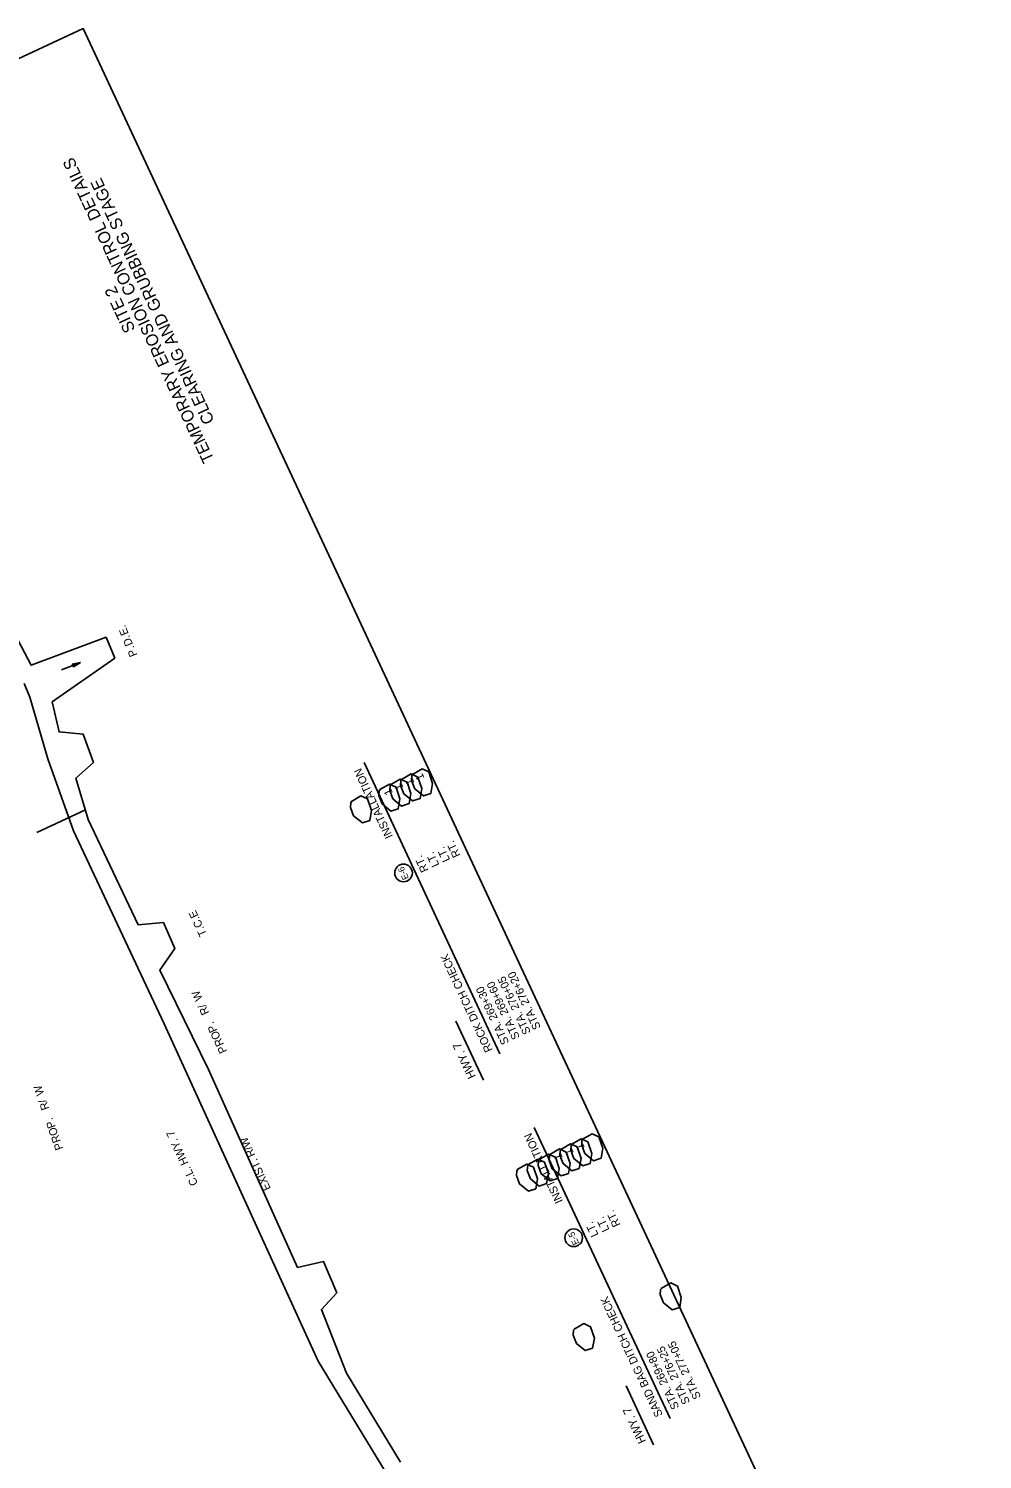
# Model space of a CAD drawing. Extents: x 964229 to 965790, y 1899262 to 1901428.
# Drawn here: x 965075 to 965790, y 1900076 to 1901149 of the extents above; entities that cross this region are included whole.
import ezdxf

# ---------------------------------------------------------------- set-up
doc = ezdxf.new("R2010")
doc.units = 0
for name, color, linetype in [('1', 7, 'Continuous'), ('43', 7, 'Continuous'), ('44', 7, 'Continuous'), ('60', 7, 'Continuous'), ('NO PLOT', 7, 'Continuous'), ('R_Draft', 7, 'Continuous'), ('R_Horz Alg Annot', 7, 'Continuous'), ('S_TREE', 7, 'Continuous')]:
    doc.layers.add(name, color=color, linetype=linetype)

msp = doc.modelspace()

# ---------------------------------------------------------------- linework, layer by layer
at = {"layer": '1'}
for centre in [(965355.7, 1900515.4), (965483.3, 1900241.8)]:
    msp.add_circle(centre, 6.61, dxfattribs=at)
at = {"layer": '43'}
for p, q in [((965107.3, 1900672), (965113.4, 1900673.2)), ((965108.1, 1900670), (965107.3, 1900672)), ((965113.4, 1900673.2), (965108.1, 1900670))]:
    msp.add_line(p, q, dxfattribs=at)
msp.add_lwpolyline([(965099.2, 1900667.8), (965113.4, 1900673.2)], dxfattribs=at)
at = {"layer": '44'}
for p, q in [((965428, 1900379.8), (965326.2, 1900598.2)), ((965415.6, 1900360), (965395, 1900404.3)), ((965555.6, 1900106.2), (965453.7, 1900324.6)), ((965543.2, 1900086.4), (965522.6, 1900130.7))]:
    msp.add_line(p, q, dxfattribs=at)
at = {"layer": 'NO PLOT'}
msp.add_lwpolyline([(965789.8, 1899702.7), (965115.5, 1901148.6), (964643.2, 1900928.4), (964770.4, 1900655.6), (964831.6, 1900684.1), (965011.2, 1900298.9), (964950, 1900270.4), (965071, 1900011), (965127, 1900037.1), (965271.8, 1899726.6), (965215.8, 1899700.5), (965317.4, 1899482.5)], close=True, dxfattribs=at)
msp.add_lwpolyline([(965789.8, 1899702.7), (965115.5, 1901148.6), (964643.2, 1900928.4), (964770.4, 1900655.6), (964831.6, 1900684.1), (965011.2, 1900298.9), (964950, 1900270.4), (965071, 1900011), (965127, 1900037.1), (965271.8, 1899726.6), (965215.8, 1899700.5), (965317.4, 1899482.5)], close=True, dxfattribs=at)
msp.add_lwpolyline([(965789.8, 1899702.7), (965115.5, 1901148.6), (964643.2, 1900928.4), (964770.4, 1900655.6), (964831.6, 1900684.1), (965011.2, 1900298.9), (964950, 1900270.4), (965071, 1900011), (965127, 1900037.1), (965271.8, 1899726.6), (965215.8, 1899700.5), (965317.4, 1899482.5)], close=True, dxfattribs=at)
for points in [[(965353.5, 1900073.5), (965312.9, 1900140.2), (965294.1, 1900188.1), (965305.6, 1900200.5), (965295.6, 1900224), (965276.2, 1900219.6), (965209.5, 1900368), (965172.9, 1900442.6), (965184.1, 1900458.7), (965175.6, 1900478.3), (965156.7, 1900476.6), (965119.2, 1900555.6), (965110, 1900586.5), (965123.2, 1900598.3), (965115.5, 1900619.4), (965097.4, 1900621.1), (965092.2, 1900643.7), (965139.2, 1900676.5), (965132.7, 1900692.1), (965076.5, 1900671.2), (965035.9, 1900747.8)], [(965071.2, 1900657.4), (965075.4, 1900647.1), (965089, 1900601), (965108.1, 1900546.9), (965176.3, 1900402.2), (965291.7, 1900149.3), (965343, 1900065.1)]]:
    msp.add_lwpolyline(points, dxfattribs=at)
at = {"layer": 'R_Horz Alg Annot'}
msp.add_lwpolyline([(965080.6, 1900545.7), (965117.1, 1900562.7)], dxfattribs=at)
at = {"layer": 'S_TREE'}
for points in [[(965354.3, 1900585.5), (965361.4, 1900589.6), (965366.4, 1900587.3), (965369.4, 1900578.7), (965368.1, 1900571.2), (965362.5, 1900569.4), (965355.9, 1900574.8), (965353.5, 1900581), (965353.8, 1900584.7), (965354.9, 1900586)], [(965362.4, 1900589.3), (965369.6, 1900593.4), (965374.6, 1900591.1), (965377.5, 1900582.5), (965376.2, 1900575), (965370.7, 1900573.2), (965364.1, 1900578.6), (965361.7, 1900584.8), (965362, 1900588.5), (965363, 1900589.8)], [(965337.9, 1900577.9), (965345.1, 1900582), (965350.1, 1900579.7), (965353, 1900571.1), (965351.8, 1900563.6), (965346.2, 1900561.8), (965339.6, 1900567.2), (965337.2, 1900573.4), (965337.5, 1900577.1), (965338.6, 1900578.4)], [(965337.9, 1900577.9), (965345.1, 1900582), (965350.1, 1900579.7), (965353, 1900571.1), (965351.8, 1900563.6), (965346.2, 1900561.8), (965339.6, 1900567.2), (965337.2, 1900573.4), (965337.5, 1900577.1), (965338.6, 1900578.4)], [(965346.1, 1900581.7), (965353.2, 1900585.8), (965358.3, 1900583.5), (965361.2, 1900574.9), (965359.9, 1900567.4), (965354.3, 1900565.6), (965347.8, 1900571), (965345.4, 1900577.2), (965345.7, 1900580.9), (965346.7, 1900582.2)], [(965346.1, 1900581.7), (965353.2, 1900585.8), (965358.3, 1900583.5), (965361.2, 1900574.9), (965359.9, 1900567.4), (965354.3, 1900565.6), (965347.8, 1900571), (965345.4, 1900577.2), (965345.7, 1900580.9), (965346.7, 1900582.2)], [(965316.6, 1900569), (965323.7, 1900573.2), (965328.8, 1900570.9), (965331.7, 1900562.2), (965330.4, 1900554.7), (965324.9, 1900553), (965318.3, 1900558.3), (965315.9, 1900564.6), (965316.2, 1900568.2), (965317.2, 1900569.6)], [(965316.6, 1900569), (965323.7, 1900573.2), (965328.8, 1900570.9), (965331.7, 1900562.2), (965330.4, 1900554.7), (965324.9, 1900553), (965318.3, 1900558.3), (965315.9, 1900564.6), (965316.2, 1900568.2), (965317.2, 1900569.6)], [(965473.7, 1900308.1), (965480.8, 1900312.2), (965485.9, 1900309.9), (965488.8, 1900301.3), (965487.5, 1900293.8), (965481.9, 1900292), (965475.4, 1900297.4), (965472.9, 1900303.6), (965473.2, 1900307.3), (965474.3, 1900308.6)], [(965473.7, 1900308.1), (965480.8, 1900312.2), (965485.9, 1900309.9), (965488.8, 1900301.3), (965487.5, 1900293.8), (965481.9, 1900292), (965475.4, 1900297.4), (965472.9, 1900303.6), (965473.2, 1900307.3), (965474.3, 1900308.6)], [(965473.7, 1900308.1), (965480.8, 1900312.2), (965485.9, 1900309.9), (965488.8, 1900301.3), (965487.5, 1900293.8), (965481.9, 1900292), (965475.4, 1900297.4), (965472.9, 1900303.6), (965473.2, 1900307.3), (965474.3, 1900308.6)], [(965481.8, 1900311.9), (965489, 1900316), (965494, 1900313.7), (965496.9, 1900305.1), (965495.6, 1900297.6), (965490.1, 1900295.8), (965483.5, 1900301.2), (965481.1, 1900307.4), (965481.4, 1900311.1), (965482.5, 1900312.4)], [(965481.8, 1900311.9), (965489, 1900316), (965494, 1900313.7), (965496.9, 1900305.1), (965495.6, 1900297.6), (965490.1, 1900295.8), (965483.5, 1900301.2), (965481.1, 1900307.4), (965481.4, 1900311.1), (965482.5, 1900312.4)], [(965490, 1900315.7), (965497.1, 1900319.8), (965502.2, 1900317.5), (965505.1, 1900308.9), (965503.8, 1900301.4), (965498.2, 1900299.6), (965491.7, 1900305), (965489.3, 1900311.2), (965489.5, 1900314.9), (965490.6, 1900316.3)], [(965490, 1900315.7), (965497.1, 1900319.8), (965502.2, 1900317.5), (965505.1, 1900308.9), (965503.8, 1900301.4), (965498.2, 1900299.6), (965491.7, 1900305), (965489.3, 1900311.2), (965489.5, 1900314.9), (965490.6, 1900316.3)], [(965449.2, 1900296.7), (965456.3, 1900300.8), (965461.4, 1900298.5), (965464.3, 1900289.9), (965463, 1900282.4), (965457.5, 1900280.6), (965450.9, 1900286), (965448.5, 1900292.2), (965448.8, 1900295.9), (965449.8, 1900297.2)], [(965449.2, 1900296.7), (965456.3, 1900300.8), (965461.4, 1900298.5), (965464.3, 1900289.9), (965463, 1900282.4), (965457.5, 1900280.6), (965450.9, 1900286), (965448.5, 1900292.2), (965448.8, 1900295.9), (965449.8, 1900297.2)], [(965457.4, 1900300.5), (965464.5, 1900304.6), (965469.6, 1900302.3), (965472.5, 1900293.7), (965471.2, 1900286.2), (965465.6, 1900284.4), (965459, 1900289.8), (965456.6, 1900296), (965456.9, 1900299.7), (965458, 1900301)], [(965457.4, 1900300.5), (965464.5, 1900304.6), (965469.6, 1900302.3), (965472.5, 1900293.7), (965471.2, 1900286.2), (965465.6, 1900284.4), (965459, 1900289.8), (965456.6, 1900296), (965456.9, 1900299.7), (965458, 1900301)], [(965457.4, 1900300.5), (965464.5, 1900304.6), (965469.6, 1900302.3), (965472.5, 1900293.7), (965471.2, 1900286.2), (965465.6, 1900284.4), (965459, 1900289.8), (965456.6, 1900296), (965456.9, 1900299.7), (965458, 1900301)], [(965465.5, 1900304.3), (965472.7, 1900308.4), (965477.7, 1900306.1), (965480.6, 1900297.5), (965479.3, 1900290), (965473.8, 1900288.2), (965467.2, 1900293.6), (965464.8, 1900299.8), (965465.1, 1900303.5), (965466.2, 1900304.8)], [(965465.5, 1900304.3), (965472.7, 1900308.4), (965477.7, 1900306.1), (965480.6, 1900297.5), (965479.3, 1900290), (965473.8, 1900288.2), (965467.2, 1900293.6), (965464.8, 1900299.8), (965465.1, 1900303.5), (965466.2, 1900304.8)], [(965465.5, 1900304.3), (965472.7, 1900308.4), (965477.7, 1900306.1), (965480.6, 1900297.5), (965479.3, 1900290), (965473.8, 1900288.2), (965467.2, 1900293.6), (965464.8, 1900299.8), (965465.1, 1900303.5), (965466.2, 1900304.8)], [(965441, 1900292.9), (965448.2, 1900297), (965453.2, 1900294.7), (965456.1, 1900286.1), (965454.9, 1900278.6), (965449.3, 1900276.8), (965442.7, 1900282.2), (965440.3, 1900288.4), (965440.6, 1900292.1), (965441.7, 1900293.4)], [(965441, 1900292.9), (965448.2, 1900297), (965453.2, 1900294.7), (965456.1, 1900286.1), (965454.9, 1900278.6), (965449.3, 1900276.8), (965442.7, 1900282.2), (965440.3, 1900288.4), (965440.6, 1900292.1), (965441.7, 1900293.4)], [(965548.9, 1900203.7), (965556.1, 1900207.9), (965561.1, 1900205.5), (965564, 1900196.9), (965562.8, 1900189.4), (965557.2, 1900187.7), (965550.6, 1900193), (965548.2, 1900199.2), (965548.5, 1900202.9), (965549.6, 1900204.3)], [(965548.9, 1900203.7), (965556.1, 1900207.9), (965561.1, 1900205.5), (965564, 1900196.9), (965562.8, 1900189.4), (965557.2, 1900187.7), (965550.6, 1900193), (965548.2, 1900199.2), (965548.5, 1900202.9), (965549.6, 1900204.3)], [(965483.7, 1900173.3), (965490.8, 1900177.4), (965495.9, 1900175.1), (965498.8, 1900166.5), (965497.5, 1900159), (965491.9, 1900157.2), (965485.4, 1900162.6), (965483, 1900168.8), (965483.2, 1900172.5), (965484.3, 1900173.8)]]:
    msp.add_lwpolyline(points, dxfattribs=at)

# ---------------------------------------------------------------- texts
at = {"layer": '1'}
for s, p in [('E-6 ', (965359.8, 1900511.6)), ('E-5 ', (965487.5, 1900237.7))]:
    msp.add_text(s, height=4.8, rotation=115, dxfattribs=at).set_placement(p)
at = {"layer": '44'}
for s, height, p in [('INSTALLATION', 6, (965347.8, 1900542.8)), ('1', 6, (965371.6, 1900586.5)), ('1', 6, (965347.8, 1900575.4)), ('1', 6, (965355.9, 1900579.2)), ('1', 6, (965364.1, 1900583)), ('LT.', 6, (965390.8, 1900525.2)), ('RT.', 6, (965398.5, 1900528.6)), ('RT.', 6, (965374.6, 1900517.5)), ('LT.', 6, (965382.7, 1900521.4)), ('ROCK DITCH CHECK', 6, (965422.6, 1900382.6)), ('STA. 276+20', 6, (965458.8, 1900399.5)), ('STA. 269+30', 6, (965435, 1900388.3)), ('STA. 269+60', 6, (965443.1, 1900392.1)), ('STA. 276+05', 6, (965451.3, 1900395.9)), ('HWY. 7', 6.25, (965410.1, 1900362.8)), ('INSTALLATION', 6, (965475.4, 1900269.2)), ('1', 6, (965483.5, 1900305.6)), ('1', 6, (965491.7, 1900309.4)), ('1', 6, (965475.3, 1900301.8)), ('LT.', 6, (965510.3, 1900247.8)), ('RT.', 6, (965518.5, 1900251.5)), ('LT.', 6, (965502.1, 1900244)), ('SAND BAG DITCH CHECK', 6, (965550.2, 1900109)), ('STA. 276+25', 6, (965570.7, 1900118.5)), ('STA. 277+05', 6, (965578.9, 1900122.3)), ('STA. 269+80', 6, (965562.6, 1900114.7)), ('HWY. 7', 6.25, (965537.7, 1900089.2))]:
    msp.add_text(s, height=height, rotation=115, dxfattribs=at).set_placement(p)
at = {"layer": '60'}
for s, p in [('TEMPORARY EROSION CONTROL DETAILS', (965213.9, 1900825.5)), ('CLEARING AND GRUBBING STAGE', (965214.1, 1900854.4)), ('SITE 2', (965154.8, 1900923))]:
    msp.add_text(s, height=9, rotation=115, dxfattribs=at).set_placement(p)
at = {"layer": 'R_Draft'}
for s, rotation, p in [('E', 112.1261, (965149.7, 1900694.9)), ('.', 112.1261, (965147.7, 1900699.8)), ('D', 112.1261, (965152.9, 1900686.9)), ('.', 112.1261, (965150.8, 1900692.1)), ('.', 112.1261, (965154, 1900684.2)), ('P', 112.1261, (965156.2, 1900678.9)), ('T.C.E', 115, (965208.4, 1900469.4)), ('W', 115.0466, (965205.2, 1900421)), ('/', 115.0466, (965207.7, 1900415.7)), ('R', 115.0466, (965210.1, 1900410.5)), ('P', 115.0466, (965216.2, 1900397.3)), ('O', 115.0466, (965218.7, 1900392)), ('.', 115.0466, (965213.8, 1900402.5)), ('R', 115.0466, (965221.1, 1900386.9)), ('P', 115.0466, (965223.5, 1900381.7)), ('W', 109.2399, (965086.3, 1900349.6)), ('/', 109.2399, (965088.2, 1900344.1)), ('R', 109.2399, (965090.1, 1900338.7)), ('.', 109.2399, (965093, 1900330.3)), ('P', 109.2399, (965094.9, 1900325)), ('O', 109.2399, (965096.8, 1900319.4)), ('C.L. HWY. 7', 114.8575, (965201.7, 1900282.4)), ('R', 109.2399, (965098.7, 1900314.1)), ('P', 109.2399, (965100.6, 1900308.7)), ('EXIST. R/W', 114.8891, (965256.3, 1900278.7))]:
    msp.add_text(s, height=6, rotation=rotation, dxfattribs=at).set_placement(p)

doc.saveas('drawing.dxf')
